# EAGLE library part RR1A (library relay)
RELAY reed, polarity, 1 x norm. open with shield
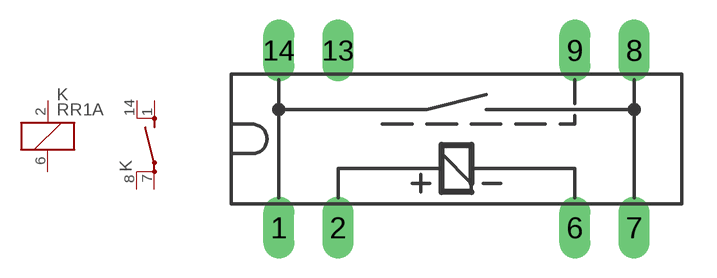
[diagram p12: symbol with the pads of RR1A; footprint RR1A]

Designator prefix K; gates 1=K 2=SD

## RR1A (OC_FARNELL: unknown; OC_NEWARK: unknown)  [RR1A]
1  2:S  pas
2  1:1  pas
6  1:2  pas
7  2:P  pas
8  2:P  pas
14  2:S  pas

## Footprint RR1A (pad centres in mm)
RELAY reed, polarity, 1 x norm. open with shield
drill 0.813 long: 1 -7.62,-3.81; 2 -5.08,-3.81; 6 5.08,-3.81; 7 7.62,-3.81; 8 7.62,3.81; 9 5.08,3.81; 13 -5.08,3.81; 14 -7.62,3.81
